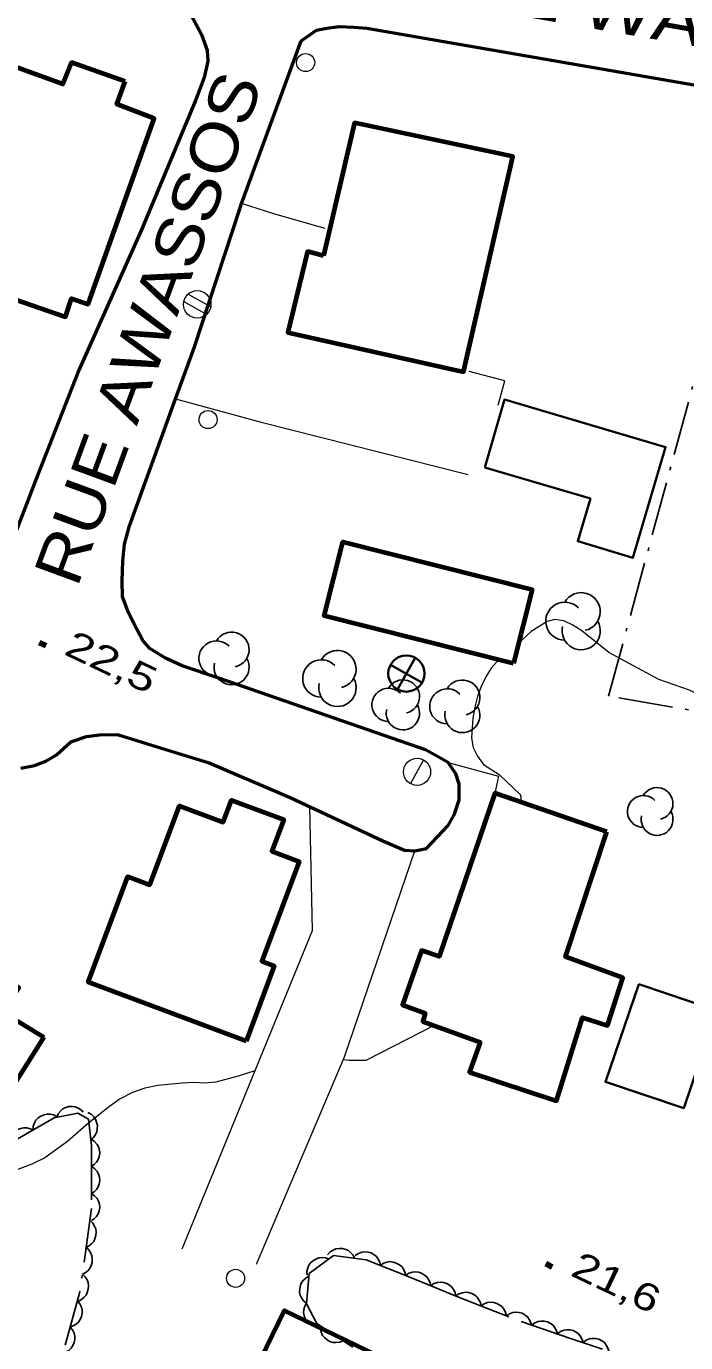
# Model space of a CAD drawing. Extents: x 356765 to 358572, y 5103174 to 5104650.
# Drawn here: x 357332.1 to 357368.6, y 5103689.6 to 5103762.5 of the extents above; entities that cross this region are included whole.
import ezdxf

# ---------------------------------------------------------------- set-up
doc = ezdxf.new("R2010")
doc.units = 0
doc.header["$LTSCALE"] = 0.6
doc.linetypes.add('DOT_DASHED', pattern=[7.7, 5, -1.2, 0.3, -1.2])
for name, color, linetype, lineweight in [('19', 7, 'Continuous', 13), ('2', 7, 'Continuous', 13), ('21', 7, 'Continuous', 53), ('3', 7, 'Continuous', 140), ('31', 7, 'Continuous', 70), ('34', 7, 'Continuous', 35), ('36', 7, 'Continuous', 13), ('41', 7, 'DOT_DASHED', 25), ('44', 7, 'Continuous', 25)]:
    doc.layers.add(name, color=color, linetype=linetype, lineweight=lineweight)

msp = doc.modelspace()

# ---------------------------------------------------------------- linework, layer by layer
at = {"layer": '19'}
for points in [[(357348.66, 5103751.28), (357345.87, 5103752.06), (357344.03, 5103752.65)], [(357358.23, 5103741.49), (357358.59, 5103742.84), (357356.63, 5103743.35)], [(357340.38, 5103741.85), (357345.11, 5103740.55), (357356.57, 5103737.66)], [(357355.46, 5103721.72), (357358.25, 5103720.95), (357358.04, 5103720.01)], [(357340.74, 5103694.79), (357347.95, 5103712.41), (357347.81, 5103719.27)], [(357344.85, 5103693.94), (357349.73, 5103705.41), (357353.61, 5103716.83)]]:
    msp.add_lwpolyline(points, dxfattribs=at)
at = {"layer": '2'}
for points in [[(357374.81, 5103724.8), (357373.73, 5103724.53), (357372.59, 5103724.32), (357372.01, 5103724.32), (357371.44, 5103724.42), (357370.87, 5103724.65), (357368.81, 5103725.71), (357367.11, 5103726.3), (357364.35, 5103727.8), (357362.85, 5103729.01), (357362.36, 5103729.32), (357361.86, 5103729.55), (357361.37, 5103729.63), (357360.94, 5103729.51), (357360.05, 5103728.96), (357359.37, 5103728.33)], [(357358.26, 5103727.41), (357357.84, 5103726.93), (357357.55, 5103726.45), (357357.29, 5103725.92), (357357.09, 5103725.36), (357356.93, 5103724.78), (357356.83, 5103724.17), (357356.75, 5103723.07), (357356.85, 5103722.55), (357357.08, 5103722.07), (357357.41, 5103721.61), (357358.29, 5103721.05), (357359.47, 5103719.92), (357359.49, 5103719.51)], [(357354.69, 5103707.16), (357350.91, 5103705.22), (357349.96, 5103705.22), (357349.66, 5103705.25)], [(357344.77, 5103704.65), (357343.84, 5103704.34), (357342.61, 5103704.01), (357342, 5103703.96), (357341.38, 5103703.99), (357340.75, 5103703.96), (357339.4, 5103703.84), (357338.68, 5103703.69), (357337.99, 5103703.44), (357337.32, 5103703.09), (357336.72, 5103702.67), (357335.57, 5103701.76), (357334.4, 5103700.73), (357333.14, 5103699.82), (357332.43, 5103699.47), (357330.96, 5103698.93), (357325.87, 5103697.3), (357324.34, 5103696.91), (357322.67, 5103696), (357321.95, 5103695.55), (357319.31, 5103693.74), (357319.02, 5103693.59), (357317.87, 5103694.09)]]:
    msp.add_lwpolyline(points, dxfattribs=at)
at = {"layer": '21'}
for points in [[(357331.21, 5103768.2), (357336.81, 5103766.37), (357339.7, 5103765.26), (357340.35, 5103764.62), (357340.98, 5103763.57), (357341.81, 5103762.01), (357342.13, 5103761.15), (357342.16, 5103760.53), (357341.95, 5103759.63), (357341.51, 5103758.46), (357338.48, 5103751.17), (357335.03, 5103743.43), (357332.65, 5103737.36), (357331.24, 5103733.7)], [(357331.81, 5103721.39), (357332.58, 5103721.54), (357333.2, 5103721.78), (357333.79, 5103722.13), (357334.58, 5103722.86), (357335.44, 5103723.16), (357336.16, 5103723.24), (357337.16, 5103723.27), (357339.07, 5103722.68), (357342.23, 5103721.7), (357346.72, 5103719.78), (357351.84, 5103717.38), (357353.04, 5103716.85), (357353.61, 5103716.83), (357354.26, 5103716.95), (357355.46, 5103718.22), (357355.79, 5103718.81), (357356.06, 5103719.64), (357356.06, 5103720.51), (357355.89, 5103721.09), (357355.46, 5103721.72), (357354.2, 5103722.42), (357342.77, 5103726.38), (357340.74, 5103727.07), (357339.82, 5103727.48), (357338.96, 5103728.03), (357338.56, 5103728.47), (357338.23, 5103729.09), (357337.77, 5103730), (357337.44, 5103730.88), (357337.43, 5103731.76), (357337.46, 5103732.88), (357337.55, 5103733.8), (357337.83, 5103734.82), (357340.38, 5103741.85), (357341.43, 5103744.73), (357343.95, 5103752.41), (357344.03, 5103752.65), (357347.33, 5103761.66), (357347.67, 5103761.91), (357348.17, 5103762.26), (357348.74, 5103762.37), (357349.42, 5103762.46), (357350.24, 5103762.41), (357350.95, 5103762.36), (357371.93, 5103758.72)]]:
    msp.add_lwpolyline(points, dxfattribs=at)
at = {"layer": '3'}
for p, q in [((357332.83, 5103728.36), (357333.19, 5103728.19)), ((357360.86, 5103693.97), (357361.22, 5103693.8))]:
    msp.add_line(p, q, dxfattribs=at)
at = {"layer": '31'}
for points in [[(357337.58, 5103759.41), (357334.61, 5103760.46), (357334.13, 5103759.26), (357331.19, 5103760.33), (357328.45, 5103752.59), (357329.49, 5103752.21), (357328.14, 5103748.5), (357334.28, 5103746.38), (357334.62, 5103747.4), (357335.54, 5103747.09), (357339.2, 5103757.37), (357337.12, 5103758.16), (357337.58, 5103759.41)], [(357348.57, 5103749.76), (357347.68, 5103750), (357346.58, 5103745.51), (357356.31, 5103743.34), (357359.03, 5103755.26), (357350.28, 5103757.13), (357348.57, 5103749.76)], [(357359.08, 5103727.2), (357348.6, 5103729.84), (357349.63, 5103733.92), (357360.11, 5103731.28), (357359.08, 5103727.2)], [(357344.28, 5103706.29), (357335.54, 5103709.55), (357337.73, 5103715.4), (357338.96, 5103714.94), (357340.6, 5103719.32), (357343.01, 5103718.41), (357343.47, 5103719.63), (357346.36, 5103718.55), (357345.7, 5103716.8), (357347.22, 5103716.24), (357345.15, 5103710.72), (357345.84, 5103710.46), (357344.28, 5103706.29)], [(357364.23, 5103717.88), (357358.04, 5103720.01), (357354.96, 5103710.97), (357353.98, 5103711.3), (357352.93, 5103708.3), (357354.19, 5103707.84), (357354.05, 5103707.38), (357357.23, 5103706.23), (357356.64, 5103704.57), (357361.46, 5103702.99), (357362.89, 5103707.59), (357364.27, 5103707.15), (357365.12, 5103709.79), (357361.96, 5103710.95), (357364.23, 5103717.88)], [(357333.08, 5103706.51), (357327.87, 5103698.22), (357324.6, 5103700.23), (357324.19, 5103699.59), (357321.54, 5103701.36), (357322, 5103702.12), (357318.55, 5103704.34), (357323.81, 5103712.36), (357328.64, 5103709.3), (357329.49, 5103710.69), (357331.71, 5103709.26), (357330.85, 5103707.88), (357333.08, 5103706.51)], [(357351.73, 5103675.29), (357341.09, 5103680.46), (357346.4, 5103691.38), (357357.04, 5103686.22), (357351.73, 5103675.29)]]:
    msp.add_lwpolyline(points, close=True, dxfattribs=at)
at = {"layer": '31', "lineweight": 35}
for points in [[(357357.48, 5103738.05), (357363.33, 5103736.32), (357362.63, 5103733.96), (357365.68, 5103733.05), (357367.49, 5103739.17), (357358.58, 5103741.8), (357357.48, 5103738.05)], [(357366, 5103709.45), (357364.16, 5103704.03), (357368.49, 5103702.57), (357370.33, 5103707.98), (357366, 5103709.45)]]:
    msp.add_lwpolyline(points, close=True, dxfattribs=at)
at = {"layer": '34'}
for p, q in [((357353.63, 5103727.5), (357352.65, 5103725.76)), ((357354.01, 5103726.14), (357352.27, 5103727.12))]:
    msp.add_line(p, q, dxfattribs=at)
msp.add_circle((357353.1454, 5103726.6316), 1, dxfattribs=at)
at = {"layer": '36'}
for p, q in [((357340.83, 5103747.23), (357342.1, 5103746.52)), ((357342.32, 5103746.93), (357341.05, 5103747.63)), ((357353.38, 5103720.53), (357354.1, 5103721.85))]:
    msp.add_line(p, q, dxfattribs=at)
for centre, radius in [((357347.5738, 5103760.4571), 0.5), ((357341.5772, 5103747.0748), 0.7588), ((357342.1738, 5103740.6971), 0.5), ((357353.7393, 5103721.195), 0.75), ((357343.6938, 5103693.1571), 0.5)]:
    msp.add_circle(centre, radius, dxfattribs=at)
at = {"layer": '41'}
msp.add_lwpolyline([(357376.97, 5103723.21), (357364.33, 5103725.39), (357369.14, 5103743.1), (357372.8, 5103756.99)], dxfattribs=at)
at = {"layer": '44'}
for points in [[(357333.8, 5103702.08), (357333.88, 5103702.27), (357334.02, 5103702.42), (357334.14, 5103702.54), (357334.3, 5103702.61), (357334.47, 5103702.66), (357334.67, 5103702.67), (357334.83, 5103702.65), (357334.99, 5103702.58), (357335.15, 5103702.49), (357335.27, 5103702.36)], [(357332.49, 5103701.37), (357332.5, 5103701.58), (357332.57, 5103701.77), (357332.65, 5103701.91), (357332.78, 5103702.04), (357332.93, 5103702.14), (357333.11, 5103702.21), (357333.27, 5103702.25), (357333.44, 5103702.24), (357333.62, 5103702.2), (357333.78, 5103702.12)], [(357335.52, 5103702.33), (357335.7, 5103702.24), (357335.85, 5103702.09), (357335.95, 5103701.96), (357336.01, 5103701.8), (357336.05, 5103701.62), (357336.04, 5103701.43), (357336.02, 5103701.27), (357335.94, 5103701.11), (357335.83, 5103700.96), (357335.69, 5103700.84)], [(357331.19, 5103700.61), (357331.21, 5103700.82), (357331.28, 5103701.01), (357331.36, 5103701.15), (357331.48, 5103701.28), (357331.63, 5103701.39), (357331.81, 5103701.45), (357331.97, 5103701.49), (357332.15, 5103701.48), (357332.33, 5103701.44), (357332.49, 5103701.37)], [(357335.73, 5103700.85), (357335.9, 5103700.73), (357336.03, 5103700.57), (357336.12, 5103700.43), (357336.16, 5103700.26), (357336.18, 5103700.08), (357336.15, 5103699.89), (357336.1, 5103699.73), (357336, 5103699.58), (357335.88, 5103699.45), (357335.73, 5103699.35)], [(357335.73, 5103699.35), (357335.9, 5103699.23), (357336.03, 5103699.07), (357336.12, 5103698.93), (357336.16, 5103698.76), (357336.18, 5103698.58), (357336.15, 5103698.39), (357336.1, 5103698.23), (357336, 5103698.08), (357335.88, 5103697.95), (357335.73, 5103697.85)], [(357335.73, 5103697.85), (357335.9, 5103697.73), (357336.03, 5103697.57), (357336.12, 5103697.43), (357336.16, 5103697.26), (357336.18, 5103697.08), (357336.15, 5103696.89), (357336.1, 5103696.73), (357336, 5103696.58), (357335.88, 5103696.45), (357335.73, 5103696.35)], [(357335.64, 5103696.35), (357335.79, 5103696.21), (357335.9, 5103696.04), (357335.96, 5103695.89), (357335.98, 5103695.71), (357335.97, 5103695.53), (357335.91, 5103695.34), (357335.85, 5103695.2), (357335.73, 5103695.06), (357335.59, 5103694.95), (357335.43, 5103694.87)], [(357335.43, 5103694.87), (357335.58, 5103694.73), (357335.69, 5103694.55), (357335.75, 5103694.4), (357335.77, 5103694.23), (357335.76, 5103694.04), (357335.7, 5103693.86), (357335.64, 5103693.71), (357335.52, 5103693.58), (357335.38, 5103693.46), (357335.22, 5103693.38)], [(357348.79, 5103694.46), (357348.93, 5103694.62), (357349.1, 5103694.72), (357349.25, 5103694.79), (357349.43, 5103694.81), (357349.61, 5103694.81), (357349.8, 5103694.75), (357349.95, 5103694.69), (357350.08, 5103694.57), (357350.2, 5103694.43), (357350.28, 5103694.27)], [(357350.32, 5103694.42), (357350.49, 5103694.54), (357350.68, 5103694.6), (357350.85, 5103694.63), (357351.02, 5103694.61), (357351.2, 5103694.56), (357351.36, 5103694.46), (357351.49, 5103694.36), (357351.59, 5103694.21), (357351.67, 5103694.05), (357351.71, 5103693.87)], [(357347.65, 5103693.33), (357347.64, 5103693.54), (357347.69, 5103693.74), (357347.75, 5103693.89), (357347.86, 5103694.03), (357348, 5103694.15), (357348.17, 5103694.24), (357348.32, 5103694.3), (357348.5, 5103694.31), (357348.68, 5103694.29), (357348.85, 5103694.23)], [(357351.71, 5103693.87), (357351.89, 5103693.99), (357352.08, 5103694.05), (357352.24, 5103694.08), (357352.42, 5103694.06), (357352.59, 5103694), (357352.76, 5103693.9), (357352.89, 5103693.81), (357352.99, 5103693.66), (357353.07, 5103693.49), (357353.11, 5103693.32)], [(357335.22, 5103693.38), (357335.37, 5103693.24), (357335.48, 5103693.07), (357335.54, 5103692.92), (357335.56, 5103692.74), (357335.55, 5103692.56), (357335.49, 5103692.37), (357335.43, 5103692.22), (357335.31, 5103692.09), (357335.17, 5103691.98), (357335.01, 5103691.9)], [(357347.62, 5103691.78), (357347.46, 5103691.91), (357347.35, 5103692.08), (357347.27, 5103692.23), (357347.24, 5103692.4), (357347.25, 5103692.58), (357347.29, 5103692.77), (357347.35, 5103692.92), (357347.46, 5103693.06), (357347.6, 5103693.18), (357347.76, 5103693.27)], [(357353.11, 5103693.32), (357353.28, 5103693.44), (357353.48, 5103693.49), (357353.64, 5103693.52), (357353.81, 5103693.5), (357353.99, 5103693.44), (357354.15, 5103693.34), (357354.28, 5103693.24), (357354.38, 5103693.1), (357354.46, 5103692.93), (357354.5, 5103692.75)], [(357354.5, 5103692.75), (357354.67, 5103692.87), (357354.86, 5103692.92), (357355.03, 5103692.95), (357355.2, 5103692.93), (357355.38, 5103692.87), (357355.54, 5103692.77), (357355.67, 5103692.67), (357355.77, 5103692.52), (357355.85, 5103692.36), (357355.88, 5103692.18)], [(357355.88, 5103692.18), (357356.05, 5103692.3), (357356.25, 5103692.36), (357356.41, 5103692.39), (357356.59, 5103692.37), (357356.76, 5103692.31), (357356.93, 5103692.22), (357357.06, 5103692.12), (357357.16, 5103691.97), (357357.24, 5103691.81), (357357.28, 5103691.63)], [(357334.95, 5103691.91), (357335.08, 5103691.75), (357335.17, 5103691.56), (357335.21, 5103691.4), (357335.21, 5103691.23), (357335.17, 5103691.05), (357335.09, 5103690.87), (357335.01, 5103690.73), (357334.87, 5103690.62), (357334.72, 5103690.52), (357334.55, 5103690.46)], [(357348.3, 5103690.44), (357348.1, 5103690.47), (357347.91, 5103690.55), (357347.77, 5103690.63), (357347.65, 5103690.76), (357347.55, 5103690.92), (357347.49, 5103691.1), (357347.46, 5103691.26), (357347.47, 5103691.44), (357347.52, 5103691.61), (357347.61, 5103691.77)], [(357357.28, 5103691.63), (357357.45, 5103691.75), (357357.64, 5103691.81), (357357.81, 5103691.84), (357357.98, 5103691.82), (357358.16, 5103691.77), (357358.32, 5103691.67), (357358.45, 5103691.57), (357358.55, 5103691.43), (357358.64, 5103691.26), (357358.68, 5103691.08)], [(357358.68, 5103691.08), (357358.85, 5103691.2), (357359.04, 5103691.26), (357359.2, 5103691.29), (357359.38, 5103691.27), (357359.56, 5103691.22), (357359.72, 5103691.12), (357359.85, 5103691.02), (357359.95, 5103690.88), (357360.03, 5103690.71), (357360.07, 5103690.54)], [(357334.55, 5103690.46), (357334.68, 5103690.3), (357334.76, 5103690.12), (357334.81, 5103689.96), (357334.8, 5103689.78), (357334.77, 5103689.6), (357334.69, 5103689.43), (357334.6, 5103689.29), (357334.47, 5103689.17), (357334.31, 5103689.08), (357334.14, 5103689.02)], [(357349.65, 5103689.7), (357349.46, 5103689.62), (357349.25, 5103689.6), (357349.09, 5103689.61), (357348.92, 5103689.66), (357348.76, 5103689.75), (357348.62, 5103689.88), (357348.51, 5103690), (357348.44, 5103690.17), (357348.4, 5103690.35), (357348.39, 5103690.53)], [(357360.08, 5103690.56), (357360.25, 5103690.69), (357360.44, 5103690.76), (357360.6, 5103690.79), (357360.77, 5103690.78), (357360.95, 5103690.74), (357361.12, 5103690.65), (357361.26, 5103690.56), (357361.37, 5103690.42), (357361.45, 5103690.25), (357361.5, 5103690.08)], [(357361.5, 5103690.08), (357361.67, 5103690.21), (357361.86, 5103690.28), (357362.02, 5103690.31), (357362.19, 5103690.3), (357362.37, 5103690.26), (357362.54, 5103690.17), (357362.68, 5103690.07), (357362.79, 5103689.94), (357362.87, 5103689.77), (357362.92, 5103689.6)], [(357362.92, 5103689.6), (357363.09, 5103689.73), (357363.28, 5103689.8), (357363.44, 5103689.83), (357363.62, 5103689.82), (357363.8, 5103689.78), (357363.96, 5103689.69), (357364.1, 5103689.6), (357364.21, 5103689.46), (357364.3, 5103689.29), (357364.34, 5103689.12)]]:
    msp.add_lwpolyline(points, dxfattribs=at)
at = {"layer": '44', "linetype": 'DOT_DASHED'}
for points in [[(357315.57, 5103689.23), (357318.03, 5103691.55), (357320.78, 5103693.32), (357325.72, 5103694.83), (357327.13, 5103695.6), (357328.57, 5103697.13), (357330.1, 5103699.18), (357331.62, 5103700.86), (357333.66, 5103702.05), (357334.97, 5103702.3), (357335.56, 5103701.97), (357335.73, 5103700.51), (357335.73, 5103697.02), (357335.07, 5103692.34), (357333.71, 5103687.47)], [(357347.77, 5103693.42), (357349.11, 5103694.42), (357350.93, 5103694.18), (357353.33, 5103693.23), (357356.03, 5103692.12), (357359.55, 5103690.74), (357362.18, 5103689.85), (357363.99, 5103689.24)], [(357350.19, 5103689.35), (357348.19, 5103690.66), (357347.62, 5103691.75), (357347.77, 5103693.42)]]:
    msp.add_lwpolyline(points, dxfattribs=at)
at = {"layer": '44'}
for centre, radius, start, end in [((357362.8204, 5103730.0612), 1.0544, 282.26917, 149.72626), ((357361.9136, 5103729.5339), 1.0544, 44.11537, 269.80396), ((357343.4756, 5103727.9576), 0.9711, 282.26917, 149.72626), ((357362.8204, 5103729.0067), 1.0544, 166.93686, 29.62122), ((357342.6404, 5103727.4721), 0.9711, 44.11537, 269.80396), ((357343.4756, 5103726.9865), 0.9711, 166.93686, 29.62122), ((357348.4421, 5103726.3635), 1.0353, 44.11537, 269.80396), ((357349.3324, 5103726.8812), 1.0353, 282.26917, 149.72626), ((357349.3324, 5103725.8459), 1.0353, 166.93686, 29.62122), ((357352.955, 5103725.3618), 0.9217, 282.26917, 149.72626), ((357356.2456, 5103725.3077), 0.9712, 282.26917, 149.72626), ((357352.1623, 5103724.9009), 0.9217, 44.11537, 269.80396), ((357355.4104, 5103724.8221), 0.9712, 44.11537, 269.80396), ((357352.955, 5103724.4401), 0.9217, 166.93686, 29.62122), ((357356.2456, 5103724.3365), 0.9712, 166.93686, 29.62122), ((357367.018, 5103719.4405), 0.881, 282.26917, 149.72626), ((357366.2603, 5103719), 0.881, 44.11537, 269.80396), ((357367.018, 5103718.5595), 0.881, 166.93686, 29.62122)]:
    msp.add_arc(centre, radius, start, end, dxfattribs=at)

# ---------------------------------------------------------------- texts
at = {"layer": '21'}
for s, rotation, width, p in [('RUE WABAN AKI', 350.126, 1.2, (357352.89, 5103764.18)), ('RUE AWASSOS', 69.802, 1.15, (357334.93, 5103731.34))]:
    msp.add_text(s, height=2.6, rotation=rotation, dxfattribs=dict(at, width=width)).set_placement(p)
at = {"layer": '3'}
for s, width, p in [('22,5   ', 1.35, (357334.13, 5103727.73)), ('21,6   ', 1.3, (357362.16, 5103693.34))]:
    msp.add_text(s, height=1.5, rotation=334.619, dxfattribs=dict(at, width=width)).set_placement(p)

doc.saveas('drawing.dxf')
